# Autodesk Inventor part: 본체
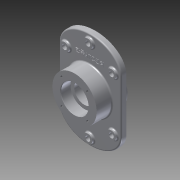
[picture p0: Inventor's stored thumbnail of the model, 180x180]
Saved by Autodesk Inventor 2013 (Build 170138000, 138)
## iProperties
Created: 2015-02
Part Number: 본체
Material: 알루미늄 6061
Document SubType Name: Modeling
Designer: Administrator
Density: 2.71 g/cm^3
Mass: 1660.43 g
Surface Area: 946.614 cm^2
Volume: 612.706 cm^3
Author: Administrator
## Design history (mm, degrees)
sketch "스케치6" dims "d59" = 50, "d60" = 50
  geometry: L1 (-70, 60)-(70, 60); L2 (70, 60)-(70, -60); L3 (70, -60)-(-70, -60); L4 (-70, -60)-(-70, 60); 5 further points; 2 other entities
  constraints: 8 end point, 3 horizontal, 3 midpoint, 2 parallel, 1 coincident, 1 horizontal alignment, 1 perpendicular, 1 vertical alignment, 8 other
  dimensions: "d29" = 120 distance of L3.end L1.start; "d31" = 140 distance of L2.end L3.end
extrude "돌출4" new body sketch "스케치6" distance "d33" = 12; taper "d34" = 0 deg
node "작업 평면3"
sketch "스케치7"
  geometry: C1 r 50 at (0, 0); 1 further point
  constraints: 1 centre point, 1 coincident
  dimensions: "d36" = 100 diameter of C1
extrude "돌출5" join sketch "스케치7" distance "d37" = 70; taper "d38" = 0 deg
node "작업 평면4"
sketch "스케치8"
  geometry: C1 r 50 at (0, 0) reference; C2 r 22.5 at (0, 0)
  constraints: 1 centre point, 1 coincident
  dimensions: "d40" = 45 diameter of C2
extrude "돌출6" cut sketch "스케치8" distance "d41" = 70; taper "d42" = 0 deg
sketch "스케치9"
  geometry: C1 r 22.5 at (0, 0) reference; C2 r 50 at (0, 0) reference; C3 r 31 at (0, 0)
  constraints: 1 centre point, 1 coincident
  dimensions: "d43" = 62 diameter of C3
extrude "돌출7" cut sketch "스케치9" distance "d44" = 22; taper "d45" = 0 deg
sketch "스케치10"
  geometry: L1 (0, 0)-(28.991, 28.991); L2 (0, 0)-(41, 0); C1 r 50 at (0, 0) reference; 1 further point
  constraints: 4 end point, 1 coincident, 1 equal length, 1 horizontal
  dimensions: "d46" = 41 distance of L1.start L1.end; "d47" = 45 deg angle of L2 L1
hole "구멍2" sketch "스케치10" at (28.991, 28.991) diameter "d48" = 4.917; stored, may be unused: countersink angle "d52" = 90 deg, drill point angle "d54" = 118 deg; dims "d49" = 10, "d50" = 4, "d51" = 2, "d53" = 13
sketch "스케치13"
  geometry: L1 (-70, 60)-(-70, -60) reference; L2 (70, -60)-(70, 60) reference; L3 (-53, 60)-(-53, -60); L4 (53, -60)-(53, 60); C1 r 50 at (0, 0) reference; C2 r 10 at (0, 93); C3 r 10 at (-53, 60); C4 r 10 at (53, 60); 2 further points; 2 other entities
  constraints: 4 end point, 3 centre point, 3 parallel, 2 coincident, 1 horizontal alignment, 1 vertical alignment, 8 other
  dimensions: "d61" = 17 distance between parallel lines of L2 L4; "d62" = 20 diameter of C2; "d63" = 20 diameter of C3; "d64" = 20 diameter of C4
extrude "돌출8" join sketch "스케치13" distance "d65" = 5; taper "d66" = 0 deg
sketch "스케치14"
  geometry: C1 r 10 at (0, 0) reference; C2 r 10 at (-53, -33) reference; C3 r 10 at (53, -33) reference; 1 further point
hole "구멍3" sketch "스케치14" at (0, 0), (-53, -33), (53, -33) diameter "d67" = 11; stored, may be unused: countersink angle "d71" = 90 deg, drill point angle "d73" = 118 deg; dims "d68" = 10, "d69" = 4, "d70" = 2, "d72" = 13
chamfer "모따기1" distance "d74" = 1; stored, may be unused: second distance "d75" = 2, angle "d76" = 45 deg
fillet "모깎기1" dims "d77" = 0.3
fillet "모깎기2" dims "d78" = 3
sketch "스케치15"
  geometry: C1 r 53 at (0, 0) reference; 1 further point
  constraints: 1 vertical alignment, 1 other
  dimensions: "d79" = 65 distance of C1.centre point (0, 65)
feature "엠보싱1" sketch "스케치15" dims "d29" = 120, "d31" = 140, "d59" = 50, "d60" = 50, "d80" = 1, "d81" = 0
node "솔리드2"
pattern_circular "원형 패턴1" dims angle "d56" = 360 deg
mirror "대칭2"
mirror "대칭3"
other parameters: "d35" = 23, "d39" = -35
